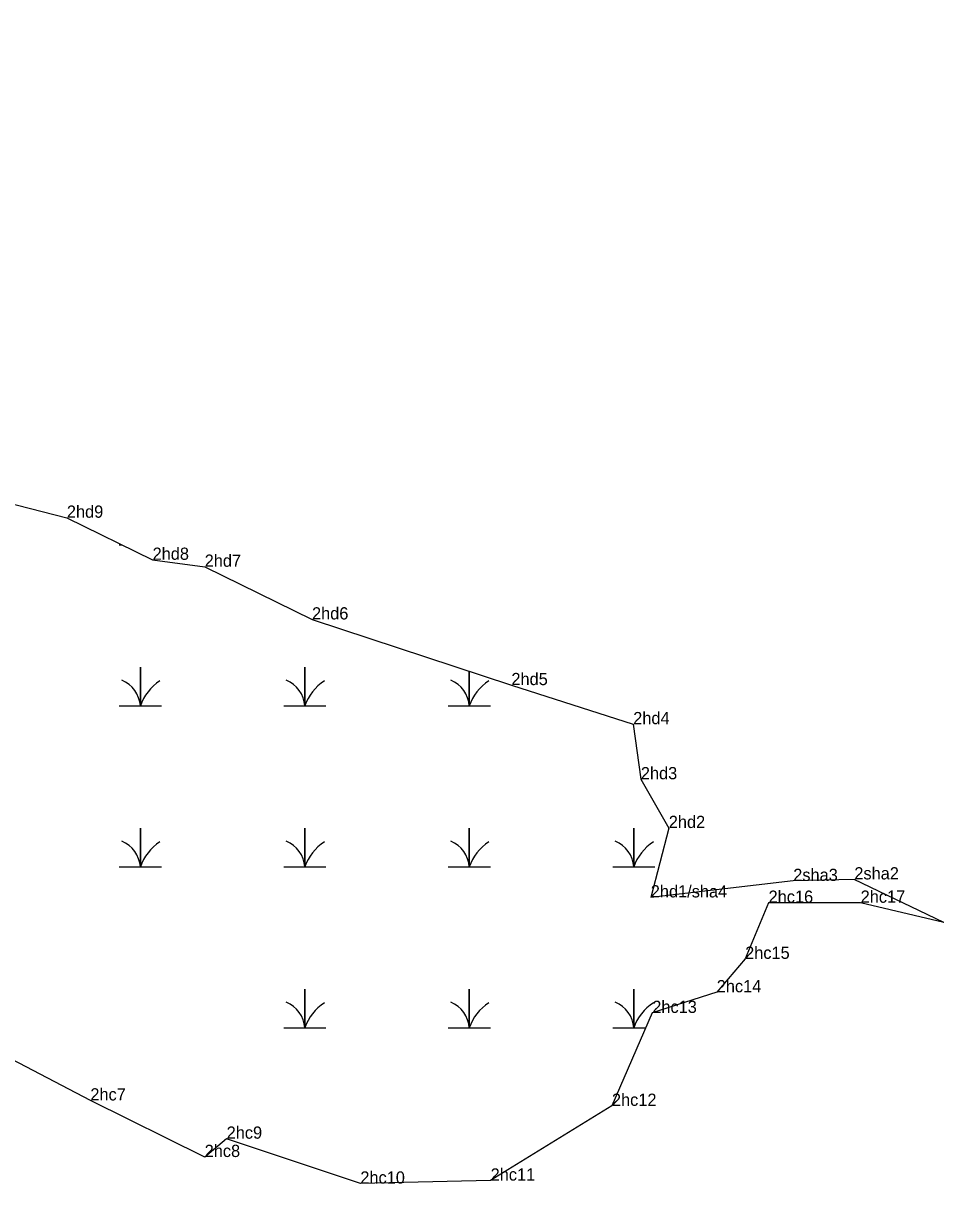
# Model space of a CAD drawing. Extents: x 2072529 to 2268796, y 436423 to 470397.
# Drawn here: x 2106799.5 to 2107175.9, y 453813.4 to 454287.8 of the extents above; entities that cross this region are included whole.
import ezdxf

# ---------------------------------------------------------------- set-up
doc = ezdxf.new("R2010")
doc.units = 0
for name, color, linetype in [('Exist Environmental Wetland Boundary', 7, 'Continuous'), ('Exist Environmental Wetland Boundary Cogo Comment', 7, 'Continuous'), ('Exist Environmental Wetland Boundary Cogo Point CELL', 7, 'Continuous'), ('Exist Hydro Jurisdictional Stream or Body of Water NEU Mitigable', 7, 'Continuous'), ('Exist Hydro Jurisdictional Stream or Body of Water NEU Mitigable Cogo Comment', 7, 'Continuous'), ('Exist Hydro Swamp or Marsh', 7, 'Continuous')]:
    doc.layers.add(name, color=color, linetype=linetype)

msp = doc.modelspace()

# ---------------------------------------------------------------- linework, layer by layer
at = {"layer": 'Exist Environmental Wetland Boundary'}
for points in [[(2106225.82, 454287.77), (2106335.08, 454245.31), (2106388.83, 454223.88), (2106440.81, 454219.04), (2106510.17, 454194.07), (2106594.46, 454156.94), (2106653.02, 454137.45), (2106698.5, 454119.85), (2106756.6, 454101.18), (2106817.34, 454085.64), (2106852.39, 454068.44), (2106873.69, 454065.6), (2106917.57, 454044.06), (2106999.1, 454017.23), (2107048.91, 454001.25), (2107052.03, 453978.75), (2107063.45, 453958.83), (2107056.1, 453930.45)], [(2107175.9, 453920.17), (2107141.9, 453928.29), (2107104.26, 453928.26), (2107094.68, 453905.35), (2107083.05, 453891.68), (2107056.7, 453883.25), (2107040.21, 453845.27), (2106990.6, 453814.72), (2106937.33, 453813.49), (2106882.67, 453831.84), (2106873.68, 453824.36), (2106826.94, 453847.47), (2106765.43, 453879.6), (2106749.46, 453897.3), (2106715.42, 453913.96), (2106685.12, 453924.67), (2106641.55, 453938.77), (2106605.07, 453940.05)]]:
    msp.add_lwpolyline(points, dxfattribs=at)
at = {"layer": 'Exist Environmental Wetland Boundary Cogo Point CELL'}
for p, q in [((2106817.34, 454085.64), (2106817.34, 454085.64)), ((2106852.39, 454068.44), (2106852.39, 454068.44)), ((2106873.69, 454065.6), (2106873.69, 454065.6)), ((2106917.57, 454044.06), (2106917.57, 454044.06)), ((2106999.1, 454017.23), (2106999.1, 454017.23)), ((2107048.91, 454001.25), (2107048.91, 454001.25)), ((2107052.03, 453978.75), (2107052.03, 453978.75)), ((2107063.45, 453958.83), (2107063.45, 453958.83)), ((2107114.34, 453937.18), (2107114.34, 453937.18)), ((2107139.32, 453937.81), (2107139.32, 453937.81)), ((2107056.1, 453930.45), (2107056.1, 453930.45)), ((2107056.1, 453930.45), (2107056.1, 453930.45)), ((2107104.26, 453928.26), (2107104.26, 453928.26)), ((2107141.9, 453928.29), (2107141.9, 453928.29)), ((2107175.9, 453920.17), (2107175.9, 453920.17)), ((2107175.9, 453920.17), (2107175.9, 453920.17)), ((2107094.68, 453905.35), (2107094.68, 453905.35)), ((2107083.05, 453891.68), (2107083.05, 453891.68)), ((2107056.7, 453883.25), (2107056.7, 453883.25)), ((2106826.94, 453847.47), (2106826.94, 453847.47)), ((2107040.21, 453845.27), (2107040.21, 453845.27)), ((2106882.67, 453831.84), (2106882.67, 453831.84)), ((2106873.68, 453824.36), (2106873.68, 453824.36)), ((2106937.33, 453813.49), (2106937.33, 453813.49)), ((2106990.6, 453814.72), (2106990.6, 453814.72))]:
    msp.add_line(p, q, dxfattribs=at)
at = {"layer": 'Exist Hydro Jurisdictional Stream or Body of Water NEU Mitigable'}
msp.add_lwpolyline([(2107175.9, 453920.17), (2107139.32, 453937.81), (2107114.34, 453937.18), (2107056.1, 453930.45)], dxfattribs=at)
at = {"layer": 'Exist Hydro Swamp or Marsh'}
for points in [[(2106838.78, 454074.53), (2106839.99, 454074.53)], [(2106838.78, 454008.73), (2106847.39, 454008.73), (2106847.39, 454024.51), (2106847.39, 454008.73), (2106855.99, 454008.73)], [(2106906.03, 454008.73), (2106914.64, 454008.73), (2106914.64, 454024.51), (2106914.64, 454008.73), (2106923.24, 454008.73)], [(2106973.28, 454008.73), (2106981.89, 454008.73), (2106981.89, 454022.89)], [(2106981.89, 454022.89), (2106981.89, 454008.73), (2106990.49, 454008.73)], [(2106838.78, 453942.93), (2106847.39, 453942.93), (2106847.39, 453958.71), (2106847.39, 453942.93), (2106855.99, 453942.93)], [(2106906.03, 453942.93), (2106914.64, 453942.93), (2106914.64, 453958.71), (2106914.64, 453942.93), (2106923.24, 453942.93)], [(2106973.28, 453942.93), (2106981.89, 453942.93), (2106981.89, 453958.71), (2106981.89, 453942.93), (2106990.49, 453942.93)], [(2107040.53, 453942.93), (2107049.14, 453942.93), (2107049.14, 453958.71), (2107049.14, 453942.93), (2107057.74, 453942.93)], [(2106906.03, 453877.13), (2106914.64, 453877.13), (2106914.64, 453892.91), (2106914.64, 453877.13), (2106923.24, 453877.13)], [(2106973.28, 453877.13), (2106981.89, 453877.13), (2106981.89, 453892.91), (2106981.89, 453877.13), (2106990.49, 453877.13)], [(2107040.53, 453877.13), (2107049.14, 453877.13), (2107049.14, 453892.91), (2107049.14, 453877.13), (2107054.04, 453877.13)]]:
    msp.add_lwpolyline(points, dxfattribs=at)
for centre, radius, start, end in [((2106835.12, 454007.84), 12.3, 4.1403, 67.535), ((2106865.63, 454002.66), 19.22, 122.1274, 161.6222), ((2106902.37, 454007.84), 12.3, 4.1403, 67.535), ((2106932.88, 454002.66), 19.22, 122.1274, 161.6222), ((2106969.62, 454007.84), 12.3, 4.1403, 67.535), ((2107000.13, 454002.66), 19.22, 122.1274, 161.6222), ((2106835.12, 453942.04), 12.3, 4.1403, 67.535), ((2106865.63, 453936.86), 19.22, 122.1274, 161.6222), ((2106902.37, 453942.04), 12.3, 4.1403, 67.535), ((2106932.88, 453936.86), 19.22, 122.1274, 161.6222), ((2106969.62, 453942.04), 12.3, 4.1403, 67.535), ((2107000.13, 453936.86), 19.22, 122.1274, 161.6222), ((2107036.87, 453942.04), 12.3, 4.1403, 67.535), ((2107067.38, 453936.86), 19.22, 122.1274, 161.6222), ((2106902.37, 453876.24), 12.3, 4.1403, 67.535), ((2106932.88, 453871.06), 19.22, 122.1274, 161.6222), ((2106969.62, 453876.24), 12.3, 4.1403, 67.535), ((2107000.13, 453871.06), 19.22, 122.1274, 161.6222), ((2107036.87, 453876.24), 12.3, 4.1403, 67.535), ((2107067.38, 453871.06), 19.22, 122.1274, 161.6222)]:
    msp.add_arc(centre, radius, start, end, dxfattribs=at)

# ---------------------------------------------------------------- texts
at = {"layer": 'Exist Environmental Wetland Boundary Cogo Comment'}
for s, p in [('2hd9', (2106817.34, 454085.64)), ('2hd8', (2106852.39, 454068.44)), ('2hd7', (2106873.69, 454065.6)), ('2hd6', (2106917.57, 454044.06)), ('2hd5', (2106999.1, 454017.23)), ('2hd4', (2107048.91, 454001.25)), ('2hd3', (2107052.03, 453978.75)), ('2hd2', (2107063.45, 453958.83)), ('2hc15', (2107094.68, 453905.35)), ('2hc14', (2107083.05, 453891.68)), ('2hc13', (2107056.7, 453883.25)), ('2hc7', (2106826.94, 453847.47)), ('2hc12', (2107040.21, 453845.27)), ('2hc9', (2106882.67, 453831.84)), ('2hc8', (2106873.68, 453824.36)), ('2hc10', (2106937.33, 453813.49)), ('2hc11', (2106990.6, 453814.72))]:
    msp.add_text(s, height=5, dxfattribs=at).set_placement(p)
at = {"layer": 'Exist Hydro Jurisdictional Stream or Body of Water NEU Mitigable Cogo Comment'}
for s, p in [('2sha3', (2107114.34, 453937.18)), ('2sha2', (2107139.32, 453937.81)), ('2hd1/sha4', (2107056.1, 453930.45)), ('2hc16', (2107104.26, 453928.26)), ('2hc17', (2107141.9, 453928.29))]:
    msp.add_text(s, height=5, dxfattribs=at).set_placement(p)

doc.saveas('drawing.dxf')
